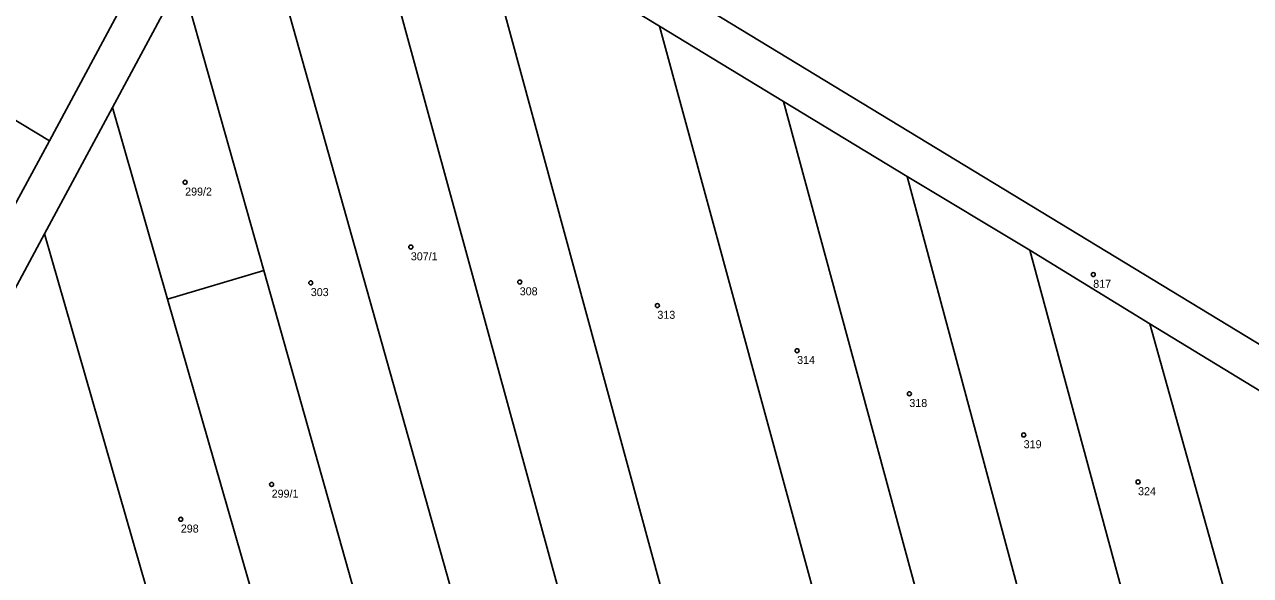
# Model space of a CAD drawing. Extents: x -550098 to -546083, y -1127254 to -1124489.
# Drawn here: x -547448.4 to -547295.2, y -1125566.2 to -1125497.4 of the extents above; entities that cross this region are included whole.
import ezdxf

# ---------------------------------------------------------------- set-up
doc = ezdxf.new("R2010")
doc.units = 0
doc.layers.add('Definiční body', color=7, linetype='Continuous')
doc.layers.add('Polygon parcely', color=7, linetype='Continuous')

msp = doc.modelspace()

# ---------------------------------------------------------------- linework, layer by layer
at = {"layer": 'Definiční body'}
for centre in [(-547428.34, -1125517.08994), (-547400.14, -1125525.17994), (-547314.87, -1125528.60994), (-547412.64, -1125529.64994), (-547386.53, -1125529.54994), (-547369.33, -1125532.48994), (-547351.87, -1125538.12994), (-547337.85, -1125543.50994), (-547323.56, -1125548.65994), (-547417.53, -1125554.83994), (-547309.27, -1125554.52994), (-547428.88, -1125559.19994)]:
    msp.add_circle(centre, 0.25, dxfattribs=at)
at = {"layer": 'Polygon parcely'}
for points in [[(-547165.99, -1125523.88), (-547252.28, -1125352.54), (-547253.34, -1125353.29), (-547407.05, -1125462.23), (-547406.74, -1125468.91), (-547249.09, -1125564.68)], [(-547585.41, -1125407.58), (-547593.34, -1125422.32), (-547445.29, -1125511.89), (-547436.19, -1125494.99)], [(-547445.29, -1125511.89), (-547593.34, -1125422.32), (-547598.79, -1125432.44), (-547450.77, -1125522.07)], [(-547245.67, -1125566.76), (-547249.09, -1125564.68), (-547406.74, -1125468.91), (-547411.12, -1125466.23), (-547419.21, -1125474.16), (-547411.31, -1125471.93), (-547407.3, -1125474.3), (-547391.7, -1125483.88), (-547369.07, -1125497.57), (-547353.56, -1125506.98), (-547338.11, -1125516.36), (-547322.81, -1125525.58), (-547307.78, -1125534.79), (-547292.14, -1125544.32), (-547281.45, -1125550.65), (-547255.23, -1125566.81), (-547236.11, -1125578.59), (-547229.52, -1125582.65), (-547223.6, -1125588.68), (-547220.52, -1125599.62), (-547226.05, -1125606.13), (-547227.14, -1125607.42), (-547209.91, -1125601.52), (-547214.02, -1125585.98)], [(-547419.21, -1125474.16), (-547420.72, -1125476.82), (-547394.96, -1125568.45), (-547381.66, -1125568.15), (-547407.3, -1125474.3), (-547411.31, -1125471.93)], [(-547368.84, -1125567.86), (-547391.7, -1125483.88), (-547407.3, -1125474.3), (-547381.66, -1125568.15)], [(-547420.72, -1125476.82), (-547428.78, -1125491.67), (-547418.51, -1125528.1), (-547406.22, -1125571.71), (-547404.04, -1125568.62), (-547394.96, -1125568.45)], [(-547391.7, -1125483.88), (-547368.84, -1125567.86), (-547349.94, -1125567.76), (-547369.07, -1125497.57)], [(-547418.51, -1125528.1), (-547428.78, -1125491.67), (-547437.42, -1125507.74), (-547430.53, -1125531.71)], [(-547337.04, -1125567.99), (-547353.56, -1125506.98), (-547369.07, -1125497.57), (-547349.94, -1125567.76)], [(-547353.56, -1125506.98), (-547337.04, -1125567.99), (-547330.56, -1125568.81), (-547323.83, -1125569.55), (-547338.11, -1125516.36)], [(-547430.53, -1125531.71), (-547437.42, -1125507.74), (-547445.91, -1125523.53), (-547424.73, -1125597.21), (-547415.38, -1125584.37)], [(-547310.48, -1125571.14), (-547322.81, -1125525.58), (-547338.11, -1125516.36), (-547323.83, -1125569.55)], [(-547445.91, -1125523.53), (-547458.06, -1125546.13), (-547437.85, -1125617.36), (-547424.73, -1125597.21)], [(-547322.81, -1125525.58), (-547310.48, -1125571.14), (-547297.19, -1125572.77), (-547307.78, -1125534.79)], [(-547406.22, -1125571.71), (-547418.51, -1125528.1), (-547430.53, -1125531.71), (-547415.38, -1125584.37)], [(-547283.76, -1125574.28), (-547292.14, -1125544.32), (-547307.78, -1125534.79), (-547297.19, -1125572.77)]]:
    msp.add_lwpolyline(points, close=True, dxfattribs=at)
msp.add_lwpolyline([(-547458.06, -1125546.13), (-547445.91, -1125523.53), (-547437.42, -1125507.74), (-547428.78, -1125491.67), (-547420.72, -1125476.82), (-547419.21, -1125474.16), (-547423.55, -1125471.51), (-547434.53, -1125491.89), (-547436.19, -1125494.99), (-547445.29, -1125511.89), (-547450.77, -1125522.07)], dxfattribs=at)

# ---------------------------------------------------------------- texts
at = {"layer": 'Definiční body'}
for s, p in [('299/2', (-547428.34, -1125518.746)), ('307/1', (-547400.14, -1125526.836)), ('303', (-547412.64, -1125531.306)), ('308', (-547386.53, -1125531.206)), ('817', (-547314.87, -1125530.266)), ('313', (-547369.33, -1125534.146)), ('314', (-547351.87, -1125539.786)), ('318', (-547337.85, -1125545.166)), ('319', (-547323.56, -1125550.316)), ('299/1', (-547417.53, -1125556.496)), ('324', (-547309.27, -1125556.186)), ('298', (-547428.88, -1125560.856))]:
    msp.add_text(s, height=0.999996, dxfattribs=at).set_placement(p)

doc.saveas('drawing.dxf')
